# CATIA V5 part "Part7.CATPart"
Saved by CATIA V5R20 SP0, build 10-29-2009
Part number: Parallel Pin Unhardened_DIN_Parallel Pin ISO 2338 - 2 h6 x 10 - St
Revision: ANY
Definition: UNKNOWN
Nomenclature: Parallel Pin Unhardened_DIN_Parallel Pin ISO 2338 - 2 h6 x 10 - St
Source: Unknown
Bounding box of the stored display mesh (mm): x 0 to 10, y -1 to 1, z -1 to 1
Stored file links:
  C:\Users\Utente\Desktop\IO LAVORO\3D X SITO CF\CUMSA\3D files BA\BA 081620\Part7.CATPart
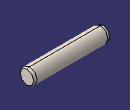
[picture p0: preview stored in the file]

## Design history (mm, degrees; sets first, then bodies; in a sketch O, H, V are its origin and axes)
Body1 "Base-Revolve" (main body)
  Solid1: solid without history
